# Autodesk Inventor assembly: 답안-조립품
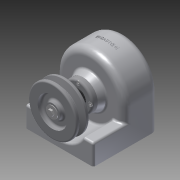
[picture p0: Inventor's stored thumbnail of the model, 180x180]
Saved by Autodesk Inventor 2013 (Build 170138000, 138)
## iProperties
Created: 2015-02
Part Number: 답안-조립품
Document SubType Name: Assembly
Designer: Administrator
Author: Administrator
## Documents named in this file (14)
- C:\Users\Administrator\Desktop\450216V1006\답안-조립품.iam
- C:\Users\Administrator\Desktop\450216V1006\1-본체.ipt
- C:\Users\Administrator\Desktop\450216V1006\축.ipt
- C:\Users\Administrator\Desktop\450216V1006\키5x5.ipt
- C:\Users\Administrator\Desktop\450216V1006\키4x4.ipt
- C:\Users\Administrator\Desktop\450216V1006\4V-벨트풀리.ipt
- C:\Users\Administrator\Desktop\450216V1006\와샤.ipt
- C:\Users\Administrator\Desktop\450216V1006\M5x0.8.ipt
- M5x0.8.ipt
- C:\Users\Administrator\Desktop\450216V1006\베어링 6001.ipt
- C:\Users\Administrator\Desktop\450216V1006\스퍼기어.ipt
- C:\Users\Administrator\Desktop\450216V1006\축커버.ipt
- C:\Users\Administrator\Desktop\450216V1006\오일실.ipt
- C:\Users\Administrator\Desktop\450216V1006\M3x0.5.ipt
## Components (7 placed, 4 different names)
1. 1-본체:1
2. 4V-벨트풀리:1 — 각도:1
3. M5x0.8:1 — 각도:3
4. M3x0.5:1
5. M3x0.5:2
6. M3x0.5:3
7. M3x0.5:4
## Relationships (2: Angle 2)
- 각도:1 [Angle]: 4V-벨트풀리:1
- 각도:3 [Angle]: M5x0.8:1
